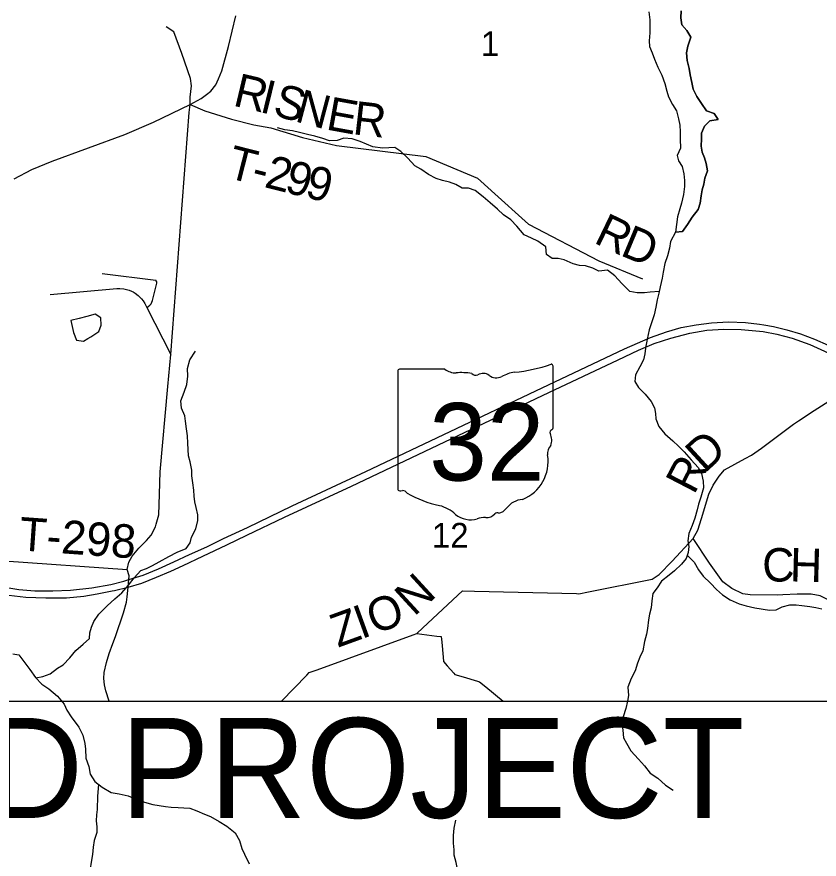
# Model space of a CAD drawing. Extents: x 0 to 34, y 0 to 22.
# Drawn here: x 3.557 to 4.921, y 18.109 to 19.541 of the extents above; entities that cross this region are included whole.
import ezdxf

# ---------------------------------------------------------------- set-up
doc = ezdxf.new("R2010")
doc.units = 0
for name, color, linetype in [('GM_X_County_Road', 7, 'Continuous'), ('GM_X_County_Road_Text', 7, 'Continuous'), ('GM_X_Minor_Lake', 7, 'Continuous'), ('GM_X_Minor_River', 7, 'Continuous'), ('GM_X_Section_Text', 7, 'Continuous'), ('GM_X_State_Location', 7, 'Continuous'), ('GM_X_State_Route', 7, 'Continuous'), ('GM_X_State_Shield', 7, 'Continuous'), ('GM_X_Township_Road', 7, 'Continuous'), ('GM_X_Township_Road_Text', 7, 'Continuous'), ('SH_Text', 7, 'Continuous')]:
    doc.layers.add(name, color=color, linetype=linetype)

msp = doc.modelspace()

# ---------------------------------------------------------------- linework, layer by layer
at = {"layer": 'GM_X_County_Road'}
for points in [[(3.794, 18.6784), (3.7983, 18.6941), (3.7996, 18.7292), (3.801, 18.7676), (3.8139, 18.9126), (3.8191, 18.967), (3.8503, 19.3783), (3.8521, 19.3919)], [(4.8859, 18.8538), (4.9128, 18.8714), (4.9622, 18.9033), (4.9832, 18.9211), (4.9995, 18.9357), (5.0016, 18.9373), (5.0071, 18.9412), (5.0101, 18.9434), (5.0236, 18.9534), (5.0339, 18.9609), (5.0645, 18.9678), (5.0789, 18.9741), (5.0897, 18.9836), (5.0961, 18.9912)], [(4.7953, 18.7899), (4.8058, 18.7957), (4.8228, 18.8074), (4.8775, 18.8483), (4.8859, 18.8538)], [(4.0068, 18.3776), (4.05, 18.4217), (4.054, 18.4259), (4.0677, 18.4309), (4.2311, 18.4902), (4.2371, 18.4924), (4.2474, 18.502), (4.3145, 18.5649), (4.3349, 18.5645), (4.5087, 18.5602), (4.5125, 18.5601), (4.5288, 18.5635), (4.6371, 18.5846), (4.6491, 18.5927), (4.6711, 18.6155), (4.7071, 18.6541), (4.7148, 18.6681), (4.721, 18.6877), (4.7333, 18.7291), (4.7407, 18.7444), (4.751, 18.7597), (4.7604, 18.7706), (4.7953, 18.7899)], [(3.7203, 18.4752), (3.7249, 18.4872), (3.7384, 18.5275), (3.7435, 18.5455), (3.7447, 18.5546), (3.7466, 18.5713), (3.7477, 18.584), (3.7483, 18.5904), (3.7447, 18.601), (3.7476, 18.6136), (3.7533, 18.6242), (3.7645, 18.6375), (3.7778, 18.6504), (3.7854, 18.6596), (3.7927, 18.6736), (3.794, 18.6784)], [(3.7144, 18.3776), (3.7085, 18.395), (3.7063, 18.4052), (3.7053, 18.4161), (3.7056, 18.4262), (3.7096, 18.4429), (3.714, 18.4585), (3.7203, 18.4752)]]:
    msp.add_lwpolyline(points, dxfattribs=at)
at = {"layer": 'GM_X_Minor_Lake'}
for points in [[(4.6313, 19.5497), (4.6331, 19.5357), (4.6331, 19.5137)], [(4.6887, 19.1759), (4.6975, 19.1879), (4.7051, 19.2004), (4.7151, 19.2132), (4.7189, 19.2242), (4.7205, 19.2367), (4.7221, 19.2466), (4.7248, 19.2564), (4.7268, 19.2666), (4.731, 19.2791), (4.7292, 19.2917), (4.7259, 19.3012), (4.7222, 19.3107), (4.7207, 19.3213), (4.7208, 19.3338), (4.7213, 19.3433), (4.7259, 19.3554), (4.7354, 19.3644), (4.7494, 19.3662), (4.7427, 19.3769), (4.7298, 19.3815), (4.7208, 19.3937), (4.713, 19.4055), (4.707, 19.4181), (4.7044, 19.4295), (4.7019, 19.4424), (4.7001, 19.4534), (4.6967, 19.4667), (4.6953, 19.4796), (4.6977, 19.491), (4.7031, 19.5065), (4.696, 19.5179), (4.6877, 19.5274), (4.6859, 19.5396), (4.6867, 19.551)], [(4.6331, 19.5137), (4.6323, 19.5004), (4.6327, 19.4909), (4.6372, 19.4796), (4.6414, 19.4693), (4.647, 19.4553), (4.6534, 19.442), (4.6587, 19.4276), (4.6621, 19.4147), (4.6651, 19.4052), (4.6719, 19.3919), (4.6787, 19.3813), (4.6817, 19.3677), (4.684, 19.3567), (4.6847, 19.3457), (4.6847, 19.3328), (4.6851, 19.318), (4.6794, 19.3055), (4.682, 19.296), (4.6881, 19.2865), (4.6911, 19.274), (4.6922, 19.2626), (4.6922, 19.2524), (4.6906, 19.2387), (4.6872, 19.2243), (4.6842, 19.2145), (4.68, 19.2008), (4.677, 19.1748)], [(4.677, 19.1748), (4.6887, 19.1759)], [(3.6779, 18.994), (3.6832, 18.9971), (3.6965, 19.0062), (3.7006, 19.0168), (3.6999, 19.0293), (3.6901, 19.0354), (3.6764, 19.0316), (3.6632, 19.0282), (3.6492, 19.0248)], [(3.6492, 19.0248), (3.6533, 19.0044), (3.6586, 18.9915), (3.6703, 18.9895), (3.6779, 18.994)]]:
    msp.add_lwpolyline(points, dxfattribs=at)
at = {"layer": 'GM_X_Minor_River'}
for points in [[(4.6867, 19.551), (4.6859, 19.5396), (4.6877, 19.5274), (4.696, 19.5179), (4.7031, 19.5065), (4.6977, 19.491), (4.6953, 19.4796), (4.6967, 19.4667), (4.7001, 19.4534), (4.7019, 19.4424), (4.7044, 19.4295), (4.707, 19.4181), (4.713, 19.4055), (4.7208, 19.3937), (4.7298, 19.3815), (4.7427, 19.3769), (4.7494, 19.3662), (4.7354, 19.3644), (4.7259, 19.3554), (4.7213, 19.3433), (4.7208, 19.3338), (4.7207, 19.3213), (4.7222, 19.3107), (4.7259, 19.3012), (4.7292, 19.2917), (4.731, 19.2791), (4.7268, 19.2666), (4.7248, 19.2564), (4.7221, 19.2466), (4.7205, 19.2367), (4.7189, 19.2242), (4.7151, 19.2132), (4.7051, 19.2004), (4.6975, 19.1879), (4.6887, 19.1759)], [(4.649, 19.074), (4.6339, 19.0731), (4.624, 19.072), (4.6119, 19.0717), (4.5991, 19.0741), (4.5856, 19.0874), (4.5739, 19.1008), (4.5615, 19.1103), (4.5463, 19.1085), (4.5365, 19.1135), (4.5241, 19.1178), (4.5139, 19.1182), (4.5029, 19.121), (4.4875, 19.1279), (4.4772, 19.1299), (4.4674, 19.1299), (4.4576, 19.1368), (4.4562, 19.1497), (4.443, 19.1597), (4.4321, 19.1647), (4.4196, 19.1701), (4.4072, 19.1849), (4.3971, 19.1956), (4.3847, 19.2044), (4.3741, 19.214), (4.3617, 19.225), (4.3497, 19.235), (4.3365, 19.2457), (4.3252, 19.2499), (4.3142, 19.2496), (4.3033, 19.2558), (4.2927, 19.26), (4.2806, 19.2627), (4.2701, 19.2662), (4.2572, 19.2731), (4.2437, 19.2819), (4.2339, 19.2877), (4.2219, 19.301), (4.2102, 19.3121), (4.1997, 19.319), (4.1898, 19.3183), (4.1785, 19.3176), (4.1626, 19.32), (4.1516, 19.3243), (4.1407, 19.3289), (4.1271, 19.3335), (4.1131, 19.3347), (4.1017, 19.331), (4.0885, 19.3304), (4.0772, 19.3342), (4.0636, 19.3381), (4.0515, 19.3408), (4.0375, 19.3443), (4.0258, 19.3471), (4.0129, 19.3487), (4.0001, 19.3522)], [(4.6887, 19.1759), (4.677, 19.1748), (4.6682, 19.1593), (4.6669, 19.1479), (4.6631, 19.1347), (4.6588, 19.1215), (4.6561, 19.1071), (4.6541, 19.0968), (4.651, 19.0817), (4.6483, 19.0711), (4.6459, 19.0601), (4.6432, 19.0476), (4.6404, 19.0343), (4.6362, 19.0207), (4.6319, 19.009), (4.6288, 18.9931), (4.6257, 18.9779), (4.6249, 18.9681), (4.6225, 18.9579), (4.6164, 18.9458), (4.6087, 18.9322), (4.6079, 18.9208), (4.6142, 18.9109), (4.6251, 18.8994), (4.6353, 18.8868), (4.6409, 18.8762), (4.6431, 18.8667), (4.6434, 18.8572), (4.6486, 18.8443), (4.6587, 18.8317), (4.6723, 18.8199), (4.6821, 18.8111), (4.6918, 18.8011), (4.7035, 18.7878), (4.7155, 18.7748), (4.7211, 18.7645), (4.7237, 18.7516), (4.7243, 18.7402), (4.7197, 18.7243), (4.7162, 18.7126), (4.7139, 18.7028), (4.7096, 18.6888), (4.705, 18.6759), (4.6996, 18.6627), (4.6976, 18.6498), (4.6994, 18.6403), (4.6986, 18.6301), (4.6948, 18.6202), (4.6871, 18.6104), (4.6753, 18.5987), (4.6658, 18.5916), (4.6529, 18.5814), (4.6456, 18.5701), (4.6383, 18.5603), (4.6364, 18.5478), (4.6355, 18.536), (4.6328, 18.5254), (4.6309, 18.5156), (4.6292, 18.5008), (4.6277, 18.4913), (4.6242, 18.4788), (4.6214, 18.4629), (4.616, 18.4523), (4.6122, 18.4421), (4.6083, 18.4289), (4.6014, 18.4157), (4.596, 18.4013), (4.5967, 18.3869), (4.5951, 18.3774), (4.5924, 18.3649), (4.5881, 18.3505), (4.5858, 18.3407), (4.5872, 18.3278), (4.5882, 18.3152), (4.5935, 18.3057), (4.601, 18.2928), (4.6141, 18.2787), (4.6242, 18.2676), (4.634, 18.255), (4.6468, 18.2462), (4.66, 18.2344), (4.6728, 18.2259)], [(3.5895, 18.417), (3.6014, 18.4191), (3.6139, 18.4236), (3.6264, 18.4337), (3.6359, 18.439), (3.647, 18.4511), (3.6577, 18.4635), (3.6702, 18.4744), (3.6809, 18.4838), (3.6813, 18.4933), (3.684, 18.5032), (3.6883, 18.513), (3.6967, 18.5255), (3.7108, 18.5394), (3.7237, 18.5514), (3.7359, 18.5616), (3.747, 18.5748), (3.7569, 18.5869), (3.7679, 18.5993), (3.7774, 18.6027), (3.7877, 18.6083), (3.7994, 18.6143), (3.8154, 18.6233), (3.8298, 18.6308), (3.845, 18.6368), (3.8519, 18.6466), (3.8542, 18.6564), (3.8615, 18.6704), (3.8646, 18.6844), (3.8647, 18.6943), (3.8618, 18.7068), (3.8595, 18.7163), (3.8589, 18.7262), (3.8582, 18.7364), (3.8564, 18.7489), (3.8549, 18.7603), (3.8546, 18.7702), (3.8517, 18.7842), (3.8491, 18.7945), (3.8484, 18.8051), (3.8477, 18.8161), (3.8474, 18.8283), (3.8456, 18.8404), (3.8438, 18.8533), (3.8428, 18.8628), (3.8372, 18.8757), (3.8361, 18.8879), (3.8415, 18.9026), (3.8461, 18.9159), (3.8478, 18.9299), (3.8471, 18.9432), (3.851, 18.9576), (3.8609, 18.9727)], [(4.6969, 18.6257), (4.7083, 18.6137), (4.7158, 18.6007), (4.7237, 18.5901), (4.7361, 18.5778), (4.7466, 18.5672), (4.7568, 18.5584), (4.77, 18.5499), (4.785, 18.5426), (4.7968, 18.5395), (4.8119, 18.536), (4.8364, 18.532), (4.8478, 18.5324), (4.858, 18.538), (4.8713, 18.5409), (4.8819, 18.5412), (4.8917, 18.54), (4.905, 18.5384), (4.9152, 18.5365), (4.9258, 18.5345)], [(3.5505, 18.4581), (3.5604, 18.4562), (3.569, 18.4447), (3.5795, 18.4314), (3.5889, 18.4177), (3.5998, 18.4062), (3.6114, 18.3982), (3.6265, 18.3856), (3.6374, 18.3722), (3.6422, 18.362), (3.6493, 18.3509), (3.6624, 18.333), (3.6692, 18.3197), (3.6729, 18.3053), (3.6739, 18.2958), (3.6746, 18.2802), (3.6794, 18.2665), (3.682, 18.2532), (3.6898, 18.2407), (3.7022, 18.2311), (3.7173, 18.2223), (3.7309, 18.2199), (3.7464, 18.2164), (3.7604, 18.2103), (3.774, 18.2056), (3.7883, 18.2017), (3.7993, 18.1998), (3.8099, 18.1982), (3.8197, 18.197), (3.8314, 18.1965), (3.8412, 18.1961), (3.8511, 18.1956), (3.8632, 18.191), (3.876, 18.1852), (3.8865, 18.181), (3.9013, 18.1729), (3.9141, 18.1645), (3.9284, 18.1534), (3.9355, 18.1405), (3.9399, 18.1268), (3.9444, 18.1173), (3.9522, 18.1005)], [(3.6962, 18.2358), (3.6942, 18.2156), (3.694, 18.1932), (3.6925, 18.1838), (3.692, 18.1739), (3.6931, 18.1637), (3.693, 18.1542), (3.6888, 18.1402), (3.6872, 18.1292), (3.6856, 18.1167), (3.6836, 18.1034), (3.682, 18.092), (3.6816, 18.0826), (3.6815, 18.0701), (3.6799, 18.0583), (3.6779, 18.0443), (3.6767, 18.0333), (3.6766, 18.0238), (3.6762, 18.0143), (3.676, 17.9939), (3.6736, 17.9711)], [(4.3661, 17.9698), (4.3612, 17.983), (4.3556, 17.9929), (4.3485, 18.0058), (4.344, 18.0153), (4.3407, 18.0256), (4.3362, 18.0385), (4.3284, 18.0515), (4.3167, 18.0656), (4.3119, 18.0755), (4.3067, 18.0888), (4.3038, 18.1028), (4.3008, 18.1154), (4.3005, 18.1248), (4.2994, 18.1358), (4.2995, 18.1487), (4.3008, 18.1616), (4.3035, 18.1749)]]:
    msp.add_lwpolyline(points, dxfattribs=at)
at = {"layer": 'GM_X_State_Route'}
for points in [[(3.5526, 19.2656), (3.5826, 19.2813), (3.6171, 19.2956), (3.7406, 19.3407), (3.7895, 19.3619), (3.8521, 19.3919), (3.8703, 19.402), (3.8798, 19.4089), (3.8869, 19.4145), (3.8952, 19.4253), (3.9, 19.4359), (3.9056, 19.4495), (3.9169, 19.4907), (3.9295, 19.5429)], [(3.5366, 18.571), (3.5606, 18.5674), (3.5877, 18.5652), (3.6185, 18.5649), (3.6486, 18.5659), (3.6848, 18.5702), (3.717, 18.5759), (3.7391, 18.5813), (3.7477, 18.584), (3.772, 18.5915), (3.798, 18.6021), (3.8243, 18.6142), (3.8509, 18.6266), (3.8802, 18.6399), (3.9085, 18.6537), (3.949, 18.6728), (4.0251, 18.7093), (4.1506, 18.768), (4.2936, 18.8358), (4.4392, 18.9049), (4.5902, 18.9763), (4.6343, 18.996), (4.6614, 19.0054), (4.6864, 19.0128), (4.7119, 19.0174), (4.7382, 19.0209), (4.7667, 19.0224), (4.796, 19.0212), (4.8196, 19.0187), (4.827, 19.0175), (4.8433, 19.0146), (4.8662, 19.0087), (4.8892, 19.002), (4.9131, 18.9931), (4.9361, 18.983)], [(3.9482, 18.6596), (4.0124, 18.69), (4.1263, 18.7432), (4.3074, 18.829), (4.4615, 18.9024), (4.5796, 18.958), (4.6138, 18.9744), (4.6403, 18.9856), (4.6688, 18.9948), (4.701, 19.0034), (4.7301, 19.008), (4.7588, 19.0101), (4.7885, 19.0096), (4.8259, 19.0057), (4.8489, 19.0014), (4.8752, 18.9945), (4.905, 18.9838), (4.9303, 18.9723), (4.964, 18.955), (4.9995, 18.9357)], [(3.1168, 18.8218), (3.196, 18.754), (3.2798, 18.6828), (3.3133, 18.655), (3.3442, 18.6326), (3.3661, 18.6193), (3.3954, 18.6033), (3.424, 18.5903), (3.449, 18.5808), (3.48, 18.5709), (3.5099, 18.5635), (3.5436, 18.5574), (3.5726, 18.5541), (3.6063, 18.5528), (3.6415, 18.5532), (3.6711, 18.556), (3.6938, 18.5596), (3.7191, 18.5648), (3.7231, 18.5658), (3.7466, 18.5713)], [(3.7466, 18.5713), (3.7695, 18.5782), (3.7948, 18.588), (3.8188, 18.5982), (3.8397, 18.6079), (3.8733, 18.6239), (3.9139, 18.6433), (3.9482, 18.6596)]]:
    msp.add_lwpolyline(points, dxfattribs=at)
at = {"layer": 'GM_X_State_Shield'}
for p, q in [((4.205, 18.9385), (4.205, 18.7384)), ((4.2848, 18.942), (4.2076, 18.942)), ((4.4686, 18.8423), (4.4686, 18.9469)), ((4.4686, 18.8423), (4.4686, 18.8423))]:
    msp.add_line(p, q, dxfattribs=at)
for centre, radius, start, end in [((4.3747, 19.2148), 0.2796, 275.8445, 288.9065), ((4.4657, 18.9474), 0.00294, 351.8621, 97.738), ((4.208, 18.939), 0.00305, 98.1301, 188.1301), ((4.3032, 18.9652), 0.0296, 231.6195, 271.1119), ((4.313, 18.8296), 0.1064, 80.4867, 94.9883), ((4.4104, 18.8809), 0.0563, 97.3462, 120.7689), ((4.3371, 18.94), 0.00855, 219.7921, 297.1024), ((4.3497, 18.9169), 0.0178, 54.4667, 119.1411), ((4.3726, 18.9486), 0.0214, 233.8562, 294.8282), ((4.4679, 18.8346), 0.00454, 107.944, 210.337), ((4.4655, 18.8419), 0.00314, 289.6038, 7.7341), ((4.4391, 18.8213), 0.0273, 340.033, 23.6496), ((4.4791, 18.7984), 0.0198, 136.8065, 186.9296), ((4.3904, 18.7851), 0.0699, 292.3089, 8.9858), ((4.208, 18.738), 0.00308, 171.9584, 258.3066), ((4.2133, 18.7269), 0.00848, 29.7484, 93.2717), ((4.2085, 18.7585), 0.0235, 267.339, 280.6039), ((4.3203, 18.9067), 0.2019, 240.4129, 257.1985), ((4.2601, 18.6485), 0.0632, 47.1842, 75.836), ((4.4199, 18.6822), 0.0383, 94.4031, 142.5768), ((4.3285, 18.7259), 0.0401, 230.7004, 286.2918), ((4.3546, 18.7109), 0.0214, 268.777, 315.5493), ((4.3739, 18.6915), 0.00601, 65.7517, 132.6484), ((4.3713, 18.719), 0.0226, 282.8732, 323.2771), ((4.3516, 18.6567), 0.0329, 85.6951, 111.2099)]:
    msp.add_arc(centre, radius, start, end, dxfattribs=at)
at = {"layer": 'GM_X_Township_Road'}
msp.add_line((3.702, 19.1047), (3.7937, 19.0935), dxfattribs=at)
for points in [[(3.8521, 19.3919), (3.8519, 19.4043), (3.854, 19.4239), (3.8526, 19.4364), (3.8378, 19.4787), (3.8238, 19.5158), (3.8113, 19.5241)], [(3.8521, 19.3919), (3.8765, 19.3813), (3.9221, 19.3672), (3.9599, 19.3576), (3.989, 19.3523), (4.0426, 19.3361), (4.1007, 19.3223), (4.2527, 19.3034), (4.3401, 19.267), (4.3634, 19.246), (4.3642, 19.2453)], [(4.3642, 19.2453), (4.427, 19.1887), (4.5467, 19.1261), (4.6208, 19.0956)], [(3.7781, 19.0469), (3.7806, 19.0482), (3.7835, 19.0508), (3.7855, 19.0533), (3.7869, 19.0557), (3.788, 19.0587), (3.7954, 19.0882), (3.7953, 19.0893), (3.7951, 19.0907), (3.7943, 19.0923), (3.7937, 19.0935)], [(3.6137, 19.069), (3.7269, 19.0789), (3.7325, 19.0791), (3.7388, 19.0785), (3.7435, 19.0775), (3.7481, 19.0761), (3.7519, 19.0747), (3.755, 19.0732), (3.7585, 19.0711), (3.7634, 19.0674), (3.7665, 19.0644), (3.7693, 19.0614), (3.7718, 19.0581), (3.7748, 19.0538), (3.7781, 19.0469), (3.8191, 18.967)], [(3.1319, 18.8526), (3.1413, 18.8445), (3.1541, 18.83), (3.1754, 18.8133), (3.1925, 18.8018), (3.2121, 18.7911), (3.2599, 18.7566), (3.2868, 18.7357), (3.4949, 18.625), (3.5138, 18.618), (3.5355, 18.6159), (3.7447, 18.601)], [(4.8595, 18.5579), (4.8506, 18.5574), (4.8038, 18.5581), (4.7914, 18.5596), (4.7726, 18.5691), (4.7574, 18.5801), (4.7346, 18.6121), (4.7071, 18.6541)], [(5.8782, 18.4588), (5.8073, 18.4419), (5.7932, 18.4365), (5.7802, 18.4292), (5.7723, 18.4238), (5.6842, 18.3245), (5.2023, 18.3605), (5.0598, 18.4567), (5.0058, 18.5041), (4.9373, 18.5493), (4.9227, 18.5564), (4.9074, 18.5594), (4.8834, 18.5594), (4.8595, 18.5579)], [(4.2371, 18.4924), (4.2456, 18.4913), (4.271, 18.4881), (4.2785, 18.4871), (4.2794, 18.4776), (4.2817, 18.4521), (4.2823, 18.4449), (4.2888, 18.4375), (4.3001, 18.4247), (4.3017, 18.4229), (4.3158, 18.4187), (4.3403, 18.4113), (4.3435, 18.4104), (4.3542, 18.4017), (4.384, 18.3776)]]:
    msp.add_lwpolyline(points, dxfattribs=at)
at = {"layer": 'SH_Text'}
msp.add_lwpolyline([(3.1565, 18.3776), (4.9408, 18.3776), (4.9408, 17.6129), (3.1565, 17.6129)], close=True, dxfattribs=at)

# ---------------------------------------------------------------- texts
at = {"layer": 'GM_X_County_Road_Text'}
for s, rotation, p in [('D', 42.6295, (4.7266, 18.7642)), ('R', 62.5814, (4.7083, 18.7269)), ('N', 42.5255, (4.2325, 18.5202)), ('O', 19.9603, (4.1646, 18.4905)), ('Z', 19.9604, (4.1029, 18.4681)), ('I', 19.9603, (4.1428, 18.4826))]:
    msp.add_text(s, height=0.0568, rotation=rotation, dxfattribs=at).set_placement(p)
at = {"layer": 'GM_X_Section_Text'}
for s, height, p in [('1', 0.0419, (4.3461, 19.4745)), ('12', 0.04186, (4.2628, 18.6386))]:
    msp.add_text(s, height=height, rotation=0, dxfattribs=at).set_placement(p)
at = {"layer": 'GM_X_State_Location'}
for s in ['s', 'r']:
    msp.add_text(s, height=0.000189, dxfattribs=at).set_placement((4.3338, 18.8252))
msp.add_text('32', height=0.000189, rotation=0, dxfattribs=at).set_placement((4.2861, 18.8114))
at = {"layer": 'GM_X_State_Shield'}
msp.add_text('32', height=0.13184, dxfattribs=at).set_placement((4.2581, 18.7525))
at = {"layer": 'GM_X_Township_Road_Text'}
for s, height, rotation, p in [('R', 0.0568, 346.6889, (3.9229, 19.3904)), ('I', 0.0568, 346.1342, (3.9682, 19.3797)), ('S', 0.0568, 344.4723, (3.9904, 19.3742)), ('N', 0.0568, 345.0898, (4.028, 19.3638)), ('E', 0.0568, 349.6917, (4.0812, 19.3498)), ('R', 0.0568, 353.4029, (4.1269, 19.3416)), ('T', 0.0568, 345.7101, (3.9122, 19.2681)), ('2', 0.0568, 345.8055, (3.9761, 19.2519)), ('9', 0.0568, 346.0816, (4.0104, 19.2432)), ('-', 0.0568, 345.7238, (3.9534, 19.2577)), ('9', 0.0568, 346.837, (4.0451, 19.2346)), ('R', 0.0568, 334.3217, (4.5361, 19.1577)), ('D', 0.0568, 337.3483, (4.5811, 19.1362)), ('T-298', 0.05682, 355.9278, (3.5598, 18.634)), ('C', 0.0568, 1.1398, (4.8248, 18.5802)), ('H', 0.0568, 358.4662, (4.8707, 18.5811))]:
    msp.add_text(s, height=height, rotation=rotation, dxfattribs=at).set_placement(p)
at = {"layer": 'SH_Text'}
msp.add_text('END PROJECT', height=0.17, dxfattribs=at).set_placement((3.1899, 18.1788))

doc.saveas('drawing.dxf')
